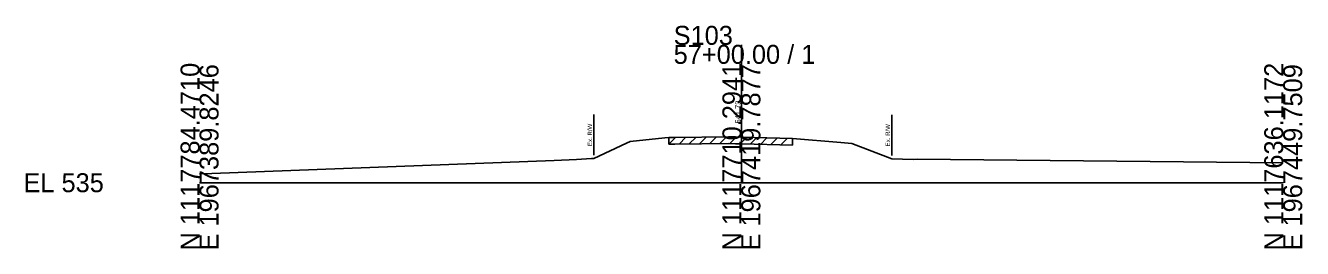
# Model space of a CAD drawing. Extents: x -26 to 163, y -10 to 24018.
# Drawn here: x -25.7 to 162.8, y 6490.3 to 6523.2 of the extents above; entities that cross this region are included whole.
import ezdxf

# ---------------------------------------------------------------- set-up
doc = ezdxf.new("R2010")
doc.units = 0
for name, color, linetype in [('RD_GPK_XS_Cell', 7, 'Continuous'), ('RD_XS_ExGround', 7, 'Continuous'), ('RD_XS_ExPaveRet', 7, 'Continuous'), ('RD_XS_ExRW', 7, 'Continuous'), ('RD_XS_TX_Elev_EX', 7, 'Continuous')]:
    doc.layers.add(name, color=color, linetype=linetype)

msp = doc.modelspace()

# ---------------------------------------------------------------- linework, layer by layer
at = {"layer": 'RD_GPK_XS_Cell'}
for p, q in [((80, 6500), (80, 6520.33)), ((0, 6500), (80, 6500)), ((80, 6500), (160, 6500))]:
    msp.add_line(p, q, dxfattribs=at)
at = {"layer": 'RD_XS_ExGround'}
msp.add_lwpolyline([(0, 6501.33), (1.81, 6501.37), (52.37, 6503.3), (55.64, 6503.44), (57.86, 6503.56), (58.21, 6503.57), (63.03, 6505.83), (63.57, 6506.07), (68.72, 6506.62), (69.3, 6506.69), (70.15, 6506.69), (78.11, 6506.78), (79.11, 6506.75), (80, 6506.73), (87.54, 6506.52), (94.69, 6505.92), (96.33, 6505.78), (102.19, 6503.51), (105.35, 6503.43), (105.94, 6503.45), (160, 6502.91)], dxfattribs=at)
at = {"layer": 'RD_XS_ExPaveRet'}
for p, q in [((69.3, 6505.69), (70.31, 6506.7)), ((69.3, 6505.69), (69.3, 6506.69)), ((70.8, 6505.7), (71.81, 6506.71)), ((72.3, 6505.72), (73.31, 6506.73)), ((73.8, 6505.73), (74.81, 6506.74)), ((75.3, 6505.75), (76.31, 6506.76)), ((76.8, 6505.76), (77.81, 6506.77)), ((78.3, 6505.77), (79.28, 6506.75)), ((79.8, 6505.73), (80.78, 6506.71)), ((81.3, 6505.69), (82.28, 6506.67)), ((82.8, 6505.65), (83.78, 6506.62)), ((84.3, 6505.61), (85.28, 6506.58)), ((85.8, 6505.57), (86.78, 6506.54)), ((87.54, 6506.52), (87.54, 6505.52)), ((69.3, 6505.69), (70.15, 6505.69)), ((70.15, 6505.69), (78.11, 6505.78)), ((78.11, 6505.78), (79.11, 6505.75)), ((79.11, 6505.75), (80, 6505.73)), ((80, 6505.73), (87.54, 6505.52))]:
    msp.add_line(p, q, dxfattribs=at)
at = {"layer": 'RD_XS_ExRW'}
for p, q in [((58.21, 6510.07), (58.21, 6504.07)), ((102.19, 6510.01), (102.19, 6504.01))]:
    msp.add_line(p, q, dxfattribs=at)

# ---------------------------------------------------------------- texts
at = {"layer": 'RD_GPK_XS_Cell'}
for s, p in [('S103', (70, 6520.33)), ('57+00.00 / 1', (70, 6517.53)), ('EL 535', (-26, 6498.6))]:
    msp.add_text(s, height=2.8, dxfattribs=at).set_placement(p)
for s, p in [('N 1117784.4710', (0, 6490)), ('E 1967389.8246', (2.8, 6490)), ('N 1117710.2941', (80, 6490)), ('E 1967419.7877', (82.8, 6490)), ('N 1117636.1172', (160, 6490)), ('E 1967449.7509', (162.8, 6490))]:
    msp.add_text(s, height=2.8, rotation=90, dxfattribs=at).set_placement(p)
at = {"layer": 'RD_XS_ExRW'}
for p in [(57.96, 6505.41), (101.94, 6505.36)]:
    msp.add_text('Ex. R/W ', height=0.65, rotation=90, dxfattribs=at).set_placement(p)
at = {"layer": 'RD_XS_TX_Elev_EX'}
msp.add_text('541.73', height=0.8, rotation=90, dxfattribs=at).set_placement((79.9, 6508.73))

doc.saveas('drawing.dxf')
